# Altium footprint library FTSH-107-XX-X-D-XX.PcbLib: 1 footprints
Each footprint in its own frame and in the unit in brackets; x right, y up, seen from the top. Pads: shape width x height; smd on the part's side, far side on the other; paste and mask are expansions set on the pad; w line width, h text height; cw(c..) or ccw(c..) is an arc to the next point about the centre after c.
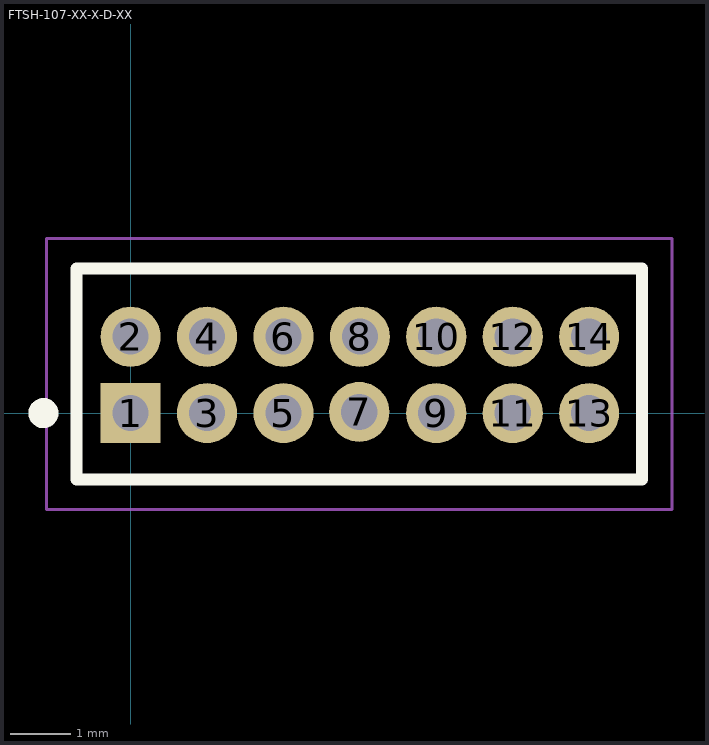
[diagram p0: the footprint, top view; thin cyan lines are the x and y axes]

## FTSH-107-XX-X-D-XX [mm] "1.27mm pitch, 14 pin, interconnect strip; double row"
height 3.05
pads (14):
  rect 1x1 / inner round 1 / far side rect 1x1 hole 0.6 mask+0: 1(0,0)
  round 1 hole 0.6 mask+0: 2(0,1.27) 3(1.27,0) 4(1.27,1.27) 5(2.54,0) 6(2.54,1.27) 7(3.8,0.02) 8(3.81,1.27) 9(5.08,0) 10(5.08,1.27) 11(6.35,0) 12(6.35,1.27) 13(7.62,0) 14(7.62,1.27)
Top Overlay:
  circle w0.25: c-1.45,0 r0.125
  lines w0.2: -0.9,-1.1 -0.9,2.4 8.5,2.4 8.5,-1.1 -0.9,-1.1
Mechanical 12:
  lines w0.001: -0.9,-1.1 -0.9,2.4 8.5,2.4 8.5,-1.1 -0.9,-1.1
Mechanical 13:
  lines w0.1: -0.9,-1.1 -0.9,2.4 8.5,2.4 8.5,-1.1 -0.9,-1.1
  text ".Designator" at 0.254,0.254 h1.52
Mechanical 15:
  lines w0.05: -1.4,-1.6 -1.4,2.9 9,2.9 9,-1.6 -1.4,-1.6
